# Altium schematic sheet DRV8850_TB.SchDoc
size 431 x 279 mm; Date: Not shown in title block; ApprovedBy: Not shown in title block; CheckedBy: Not shown in title block; Author: Not shown in title block; CompanyName: Not shown in title block; Engineer: Not shown in title block; Organization: Not shown in title block; Address1: Not shown in title block; Address2: Not shown in title block; Address3: Not shown in title block; Address4: Not shown in title block; DocumentNumber: 1; Revision: Use project parameter SCH_Rev; SheetNumber: 2; SheetTotal: 3; PageSetup: Record=PageOptions¦CenterHorizontal=True¦CenterVertical=True¦PrintScale=1.00¦XCorrection=1.00¦YCorrection=1.00¦PrintKind=0¦BorderSize=5000000¦LeftOffset=0¦BottomOffset=0¦Orientation=2¦PaperLength=1000¦PaperWidth=1000¦Scale=100¦PaperSource=15¦PrintQuality=600¦MediaType=1¦DitherType=10¦PaperKind=Letter¦PrintScaleMode=1
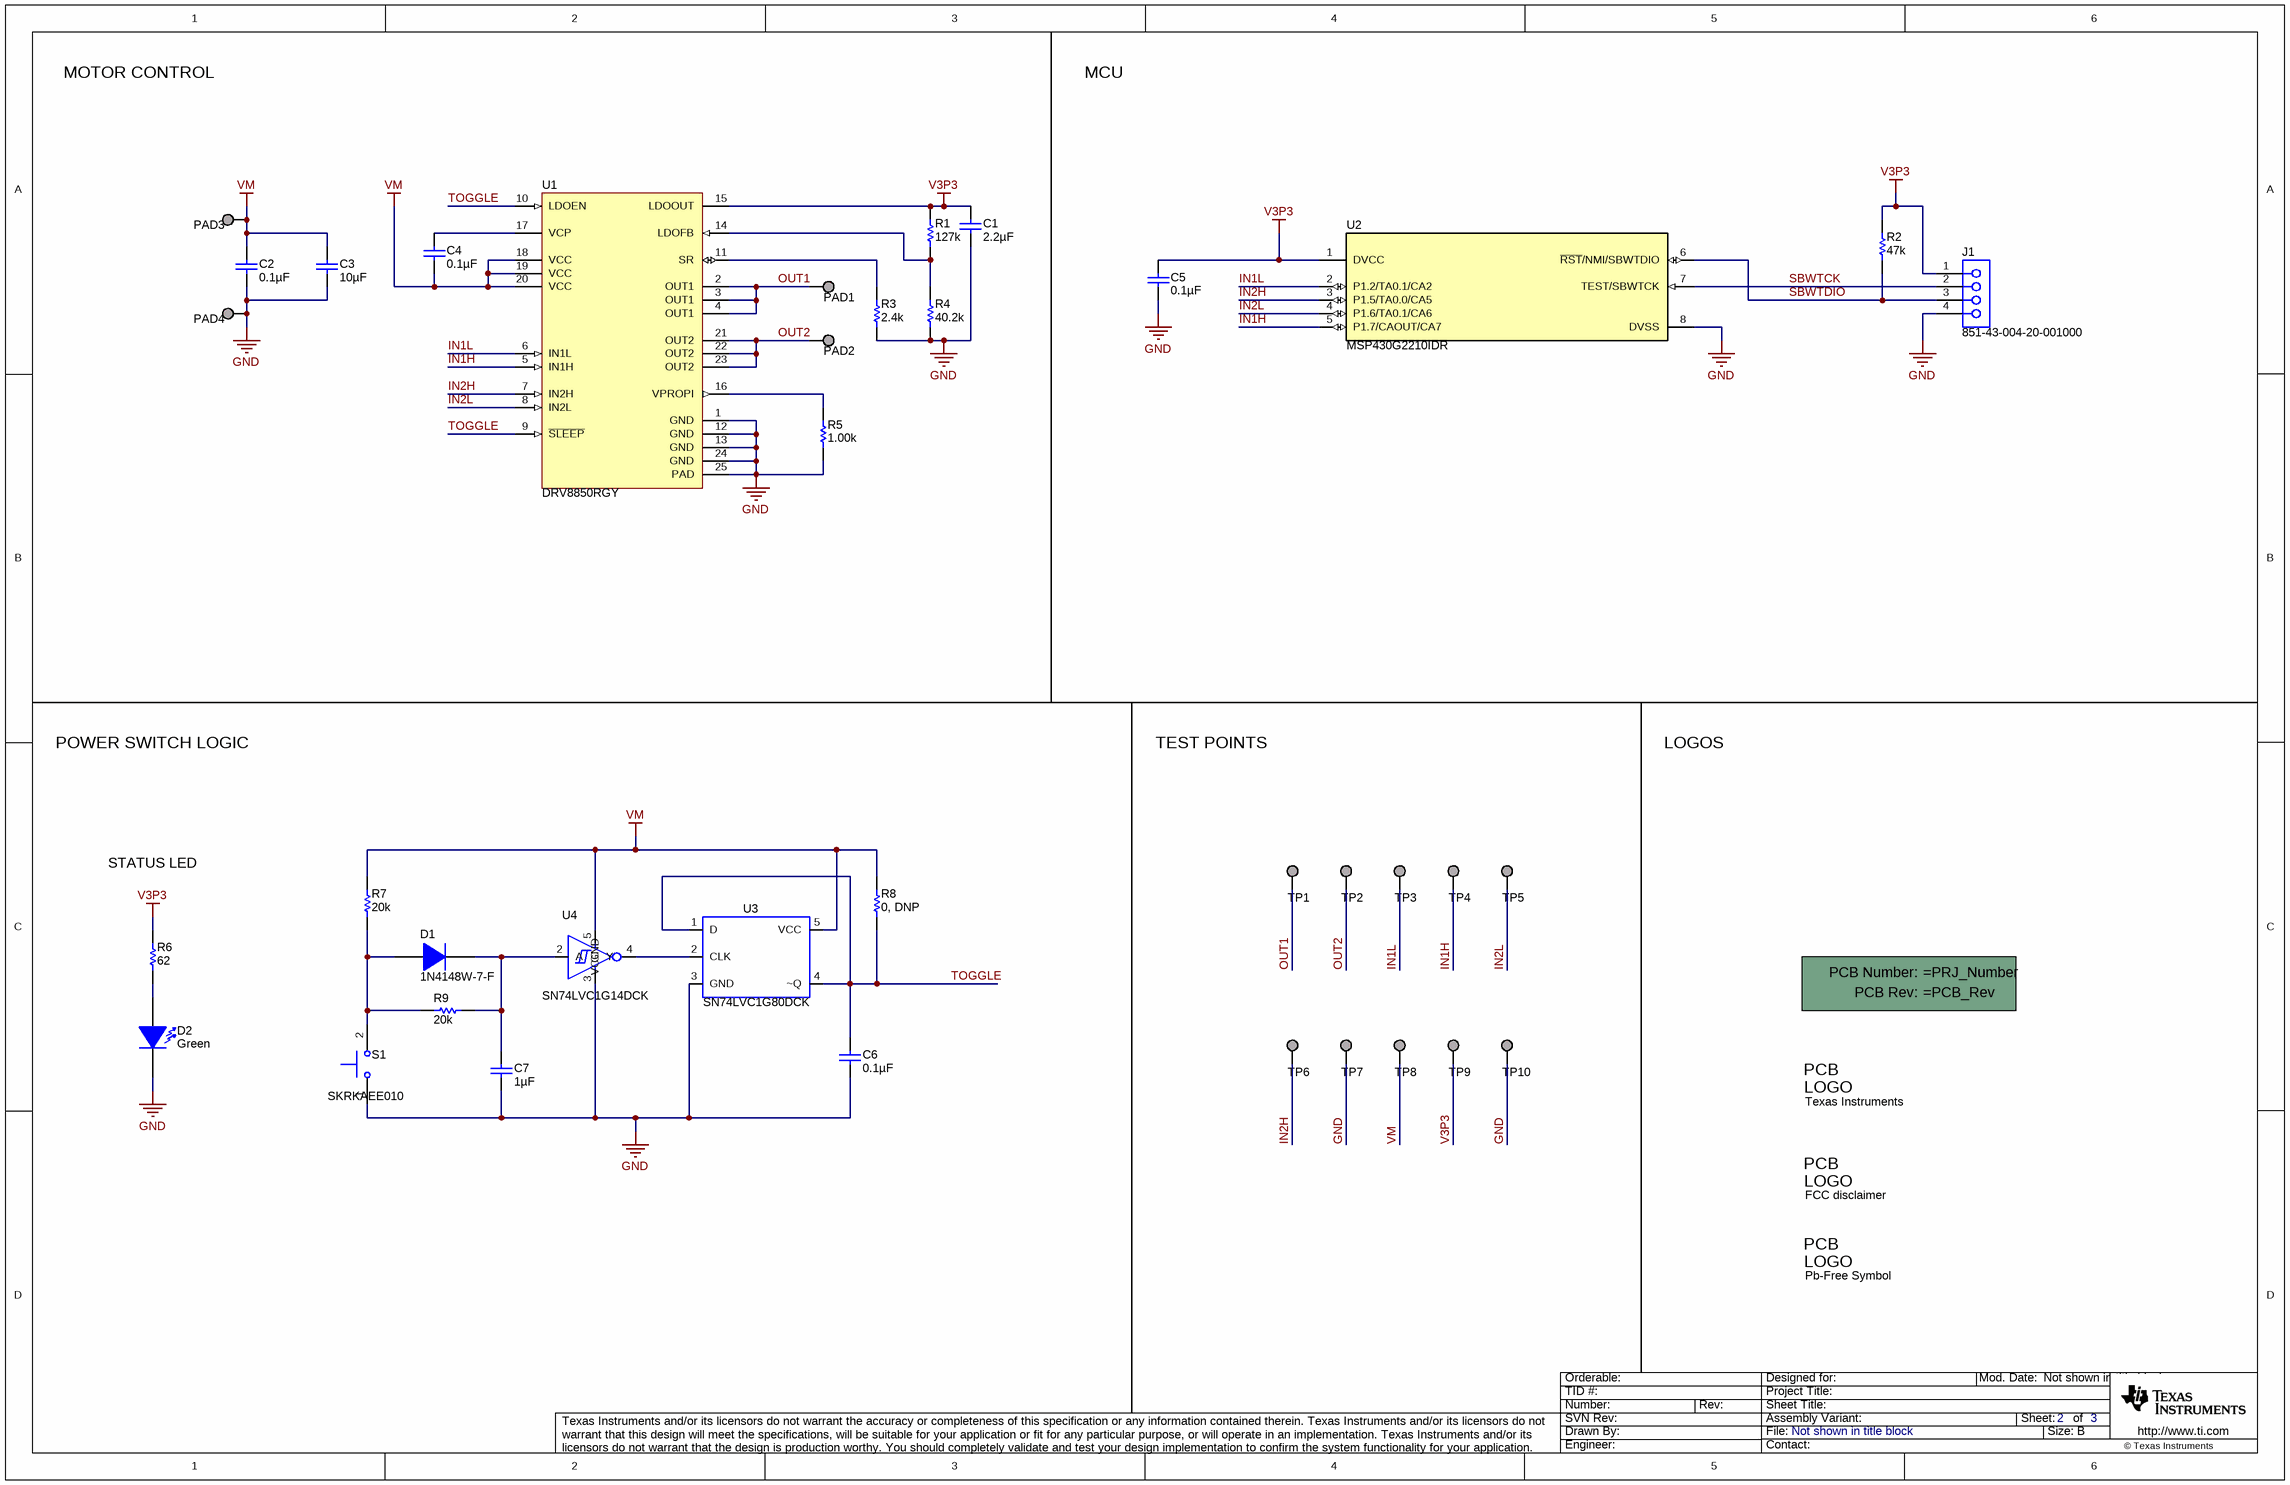
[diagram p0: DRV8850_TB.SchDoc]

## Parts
!PCB1  Printed Circuit Board  (value not drawn)  (mechanical)
C1  ValueDisplayed: 2.2µF  [0402L]  (hidden comment: 885012105013)
C2  ValueDisplayed: 0.1µF  [0402L]  (hidden comment: 885012105016)
C3  ValueDisplayed: 10µF  [0805_145L]  (hidden comment: 885012207026)
C4  ValueDisplayed: 0.1µF  [0402L]  (hidden comment: 885012105016)
C5  ValueDisplayed: 0.1µF  [0603_095]  (hidden comment: 885012206046)
C6  ValueDisplayed: 0.1µF  [0603_095]  (hidden comment: 885012206046)
C7  ValueDisplayed: 1µF  [0603_095]  (hidden comment: 885012106017)
D1  1N4148W-7-F  [SOD-123]
D2  value Green  [WL-SMCW_GREEN]  (hidden comment: 150060VS75000)
J1  851-43-004-20-001000  [CONN_851-43-004-20-001000]
Logo1  Texas Instruments  [TI_Symbol_Overlay_Small]  (no BOM)
Logo3  FCC disclaimer  [FCC_disclaimer_stacked]  (no BOM)
Logo4  Pb-Free Symbol  [Pb-Free_Overlay_Small]  (no BOM)
PAD1  OUT1  [TESTPOINT]  (value not drawn)  (no BOM)
PAD2  OUT2  [TESTPOINT]  (value not drawn)  (no BOM)
PAD3  VM  [TESTPOINT]  (value not drawn)  (no BOM)
PAD4  GND  [TESTPOINT]  (value not drawn)  (no BOM)
R1  value 127k  [0402L]  (hidden comment: CRCW0402127KFKED)
R2  value 47k  [0603L]  (hidden comment: CRCW060347K0JNEA)
R3  value 2.4k  [0402L]  (hidden comment: CRCW04022K40JNED)
R4  value 40.2k  [0402L]  (hidden comment: CRCW040240K2FKED)
R5  value 1.00k  [0402L]  (hidden comment: CRCW04021K00FKED)
R6  ValueDisplayed: 62  [0603L]  (hidden comment: CRCW060362R0JNEA)
R7  value 20k  [0603L]  (hidden comment: CRCW060320K0JNEA)
R8  value 0, DNP  [0603L]  (hidden comment: DNP)
R9  value 20k  [0603L]  (hidden comment: CRCW060320K0JNEA)
S1  SKRKAEE010  [SW_SKRKAEE010]
TP1  OUT1  [TP_25MIL-SMT]  (value not drawn)  (no BOM)
TP2  OUT2  [TP_25MIL-SMT]  (value not drawn)  (no BOM)
TP3  1L  [TP_25MIL-SMT]  (value not drawn)  (no BOM)
TP4  1H  [TP_25MIL-SMT]  (value not drawn)  (no BOM)
TP5  2L  [TP_25MIL-SMT]  (value not drawn)  (no BOM)
TP6  2H  [TP_25MIL-SMT]  (value not drawn)  (no BOM)
TP7  GND  [TP_25MIL-SMT]  (value not drawn)  (no BOM)
TP8  VM  [TP_25MIL-SMT]  (value not drawn)  (no BOM)
TP9  V3P3  [TP_25MIL-SMT]  (value not drawn)  (no BOM)
TP10  GND  [TP_25MIL-SMT]  (value not drawn)  (no BOM)
U1  DRV8850RGY  [RGY0024B]
U2  MSP430G2210IDR  [D0008A_N]
U3  SN74LVC1G80DCK  [DCK0005A_N]
U4  SN74LVC1G14DCK  [DCK0005A_N]

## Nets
GND: C1.2 C2.2 C3.2 C5.2 C6.2 C7.2 D2.1(K) J1.4 PAD4.1 R3.2 R4.1 R5.1 S1.1 TP7.1 TP10.1 U1.1(GND) U1.12(GND) U1.13(GND) U1.24(GND) U1.25(PAD) U2.8(DVSS) U3.3(GND) U4.3(GND)
V3P3: C1.1 C5.1 J1.1 R1.2 R2.1 R6.2 TP9.1 U1.15(LDOOUT) U2.1(DVCC)
VM: C2.1 C3.1 C4.2 PAD3.1 R7.2 R8.2 TP8.1 U1.18(VCC) U1.19(VCC) U1.20(VCC) U3.5(VCC) U4.5(VCC)
IN1H: TP4.1 U1.5(IN1H) U2.5(P1.7/CAOUT/CA7)
IN1L: TP3.1 U1.6(IN1L) U2.2(P1.2/TA0.1/CA2)
IN2H: TP6.1 U1.7(IN2H) U2.3(P1.5/TA0.0/CA5)
IN2L: TP5.1 U1.8(IN2L) U2.4(P1.6/TA0.1/CA6)
OUT1: PAD1.1 TP1.1 U1.2(OUT1) U1.3(OUT1) U1.4(OUT1)
OUT2: PAD2.1 TP2.1 U1.21(OUT2) U1.22(OUT2) U1.23(OUT2)
SBWTCK: J1.2 U2.7(TEST/SBWTCK)
SBWTDIO: J1.3 R2.2 U2.6(~{RST}/NMI/SBWTDIO)
TOGGLE: C6.1 R8.1 U1.9(~{SLEEP}) U1.10(LDOEN) U3.1(D) U3.4(~Q)
NetC4_1: C4.1 U1.17(VCP)
NetC7_1: C7.1 D1.1(K) R9.1 U4.2(A)
NetD1_2: D1.2(A) R7.1 R9.2 S1.2
NetD2_2: D2.2(A) R6.1
NetR1_1: R1.1 R4.2 U1.14(LDOFB)
NetR3_1: R3.1 U1.11(SR)
NetR5_2: R5.2 U1.16(VPROPI)
NetU3_2: U3.2(CLK) U4.4(Y)

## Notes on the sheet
- MOTOR CONTROL
- MCU
- POWER SWITCH LOGIC
- TEST POINTS
- LOGOS
- STATUS LED

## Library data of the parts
!PCB1 = PCB: Manufacturer: Any; SymbolCreator: a0412235
C1 = 885012105013: CAP, CERM, 2.2 µF, 10 V, +/- 20%, X5R, 0402; Manufacturer: Wurth Elektronik; Polarized: N; CompType: Capacitor; Value: 2.2uF; U/M: EA; Cap_F: 0.0000022; Tolerance_%: 20; Value1: Unknown; VDC_V: 10; Value2: 10V; TaMin_C: -55; TaMax_C: 85; Cap_Case: 0402
C2 C4 = 885012105016: CAP, CERM, 0.1 µF, 16 V, +/- 20%, X5R, 0402; Manufacturer: Wurth Elektronik; Polarized: N; CompType: Capacitor; Value: 0.1uF; U/M: EA; Cap_F: 0.0000001; Tolerance_%: 20; Value1: Unknown; VDC_V: 16; Value2: 16V; TaMin_C: -55; TaMax_C: 85; Cap_Case: 0402
C3 = 885012207026: CAP, CERM, 10 µF, 10 V, +/- 10%, X7R, 0805; Manufacturer: Wurth Elektronik; Polarized: N; CompType: Capacitor; Value: 10uF; U/M: EA; Cap_F: 0.00001; Tolerance_%: 10; Value1: Unknown; Value2: 10V; TaMin_C: -55; TaMax_C: 125; Cap_Case: 0805
C5 C6 = 885012206046: CAP, CERM, 0.1 µF, 16 V, +/- 10%, X7R, 0603_095; Manufacturer: Wurth Elektronik; Polarized: N; CompType: Capacitor; Value: 0.1uF; U/M: EA; Cap_F: 0.0000001; Tolerance_%: 10; Value1: Unknown; VDC_V: 16; Value2: 16V; TaMin_C: -55; TaMax_C: 125; Cap_Case: 0603
C7 = 885012106017: CAP, CERM, 1 µF, 16 V, +/- 20%, X5R, 0603_095; Manufacturer: Wurth Elektronik; Polarized: N; CompType: Capacitor; Value: 1uF; U/M: EA; Cap_F: 0.000001; Tolerance_%: 20; Value1: Unknown; VDC_V: 16; Value2: 16V; TaMin_C: -55; TaMax_C: 85; Cap_Case: 0603
D1 = 1N4148W-7-F: Diode, Ultrafast, 100 V, 0.15 A, SOD-123; Manufacturer: Diodes Inc.; U/M: EA; Vf_V: 1.25; Value: 100V; Value1: 0.15A; Value2: 1.25V; Io_A: 0.15; Vr_V: 100; TJmax_C: 150
D2 = 150060VS75000: LED, Green, SMD; Manufacturer: Wurth Elektronik; Type: AlInGaP; Vf_V: 2; Value2: 2V; Io_A: 0.02; Value1: W; U/M: EA
J1 = 851-43-004-20-001000: SOCKET .050" GRID SIP 4 POS R/A, TH; Manufacturer: Mill-Max; SymbolCreator: a0411947; CompType: Header; U/M: EA
Logo1 = TI_Logo: Texas Instrument Corporate Signature; SymbolCreator: a0412235
Logo3 = FCC_disclaimer: SymbolCreator: codlsc
Logo4 = Pb-Free: SymbolCreator: a0412235
PAD1-PAD4 TP1-TP10 = TESTPOINT: TEST POINT.  No entry in BOM.
R1 = CRCW0402127KFKED: RES, 127k ohm, 1%, 0.063W, 0402; Manufacturer: Vishay-Dale; CompType: Resistor; Res_ohm: 127000; Tolerance_%: 1; Power_W: 0.063; VDC_V: 50; TempCo: 100 ppm/C; EIA_Code: E96; U/M: EA
R2 = CRCW060347K0JNEA: RES, 47k ohm, 5%, 0.1W, 0603; Manufacturer: Vishay-Dale; CompType: Resistor; Res_ohm: 47000; Value_Code: 47k0; Tolerance_%: 5; Power_W: 0.1; VDC_V: 75; TempCo: 200 ppm/C; EIA_Code: E24; U/M: EA
R3 = CRCW04022K40JNED: RES, 2.4k ohm, 5%, 0.063W, 0402; Manufacturer: Vishay-Dale; CompType: Resistor; Res_ohm: 2400; Value_Code: 2k40; Tolerance_%: 5; Power_W: 0.063; VDC_V: 50; TempCo: 200 ppm/C; EIA_Code: E24; U/M: EA
R4 = CRCW040240K2FKED: RES, 40.2k ohm, 1%, 0.063W, 0402; Manufacturer: Vishay-Dale; CompType: Resistor; Res_ohm: 40200; Value_Code: 40k2; Tolerance_%: 1; Power_W: 0.063; VDC_V: 50; TempCo: 100 ppm/C; EIA_Code: E96; U/M: EA
R5 = CRCW04021K00FKED: RES, 1.00k ohm, 1%, 0.063W, 0402; Manufacturer: Vishay-Dale; CompType: Resistor; Res_ohm: 1000; Value_Code: 1k00; Tolerance_%: 1; Power_W: 0.063; VDC_V: 50; TempCo: 100 ppm/C; EIA_Code: E96; U/M: EA
R6 = CRCW060362R0JNEA: RES, 62, 5%, 0.1 W, 0603; Manufacturer: Vishay-Dale; CompType: Resistor; Value: 62; Value_Code: 62R0; Tolerance_%: 5; Power_W: 0.1; Value2: 0.1W; VDC_V: 75; TempCo: 200 ppm/C; EIA_Code: E24; U/M: EA
R7 R9 = CRCW060320K0JNEA: RES, 20k ohm, 5%, 0.1W, 0603; Manufacturer: Vishay-Dale; CompType: Resistor; Res_ohm: 20000; Value_Code: 20k0; Tolerance_%: 5; Power_W: 0.1; VDC_V: 75; TempCo: 200 ppm/C; EIA_Code: E24; U/M: EA
R8 = CRCW06030000Z0EA: RES, 0 ohm, 5%, 0.1W, 0603; CompType: Resistor; Value_Code: 0000; Tolerance_%: 5; Power_W: 0.1; VDC_V: 75; TempCo: 200 ppm/C; EIA_Code: E24; U/M: EA
S1 = SKRKAEE010: Switch, Push Button, SMD; Manufacturer: Alps; Alternate Manufacturer: Any; Alternate PartNumber: Equivalent; SymbolCreator: a0412235; Circuit: SPST-NO; VDC_V: 12; SwitchFunction: Off-Mom; PositionCount: 1; CurrentRating_mA: 50
U1 = DRV8850RGY: Low-Voltage H-Bridge IC With LDO Regulator, RGY0024B; Manufacturer: Texas Instruments; SymbolCreator: a0411947; U/M: EA
U2 = MSP430G2210IDR: MIXED SIGNAL MICROCONTROLLER, D0008A; Manufacturer: Texas Instruments; SymbolCreator: Altium; CompType: IC; U/M: EA
U3 = SN74LVC1G80DBV: IC, Single Positive-Edge-Triggered D-Type Flip-Flop; Manufacturer: TI; Alternate Manufacturer: None; Area: 23200
U4 = SN74LVC1G14DCK: IC, Single Schmitt-Trigger Inverter; Manufacturer: TI; Alternate Manufacturer: None; Area: 19,500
